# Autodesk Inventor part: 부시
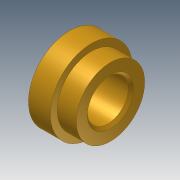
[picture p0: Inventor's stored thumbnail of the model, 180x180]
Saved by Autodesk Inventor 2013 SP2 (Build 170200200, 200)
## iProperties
Created: 2011-04
Part Number: 부시
Document SubType Name: Modeling
Density: 1 g/cm^3
Material: 일반
Author: pww
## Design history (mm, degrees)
sketch "스케치1"
  geometry: L1 (0, 0)-(15, 0); L2 (0, 7.5)-(15, 7.5); L3 (15, 7.5)-(15, 12.5); L4 (15, 12.5)-(8, 12.5); L5 (8, 12.5)-(8, 15); L6 (8, 15)-(0, 15); L7 (0, 15)-(0, 7.5)
  constraints: 14 end point, 4 parallel, 2 vertical alignment, 1 horizontal, 1 perpendicular, 1 vertical
  dimensions: "d0" = 15 distance of L1.start L1.end; "d1" = 15 diameter of L2 L1; "d2" = 25 diameter of L4 L1; "d3" = 8 distance of L5.end L6.end; "d4" = 30 diameter of L6 L1
revolve "회전1" sketch "스케치1" stored, may be unused: angle "d5" = 90 deg
chamfer "모따기1" distance "d6" = 1; stored, may be unused: second distance "d7" = 2, angle "d8" = 45 deg
node "솔리드1"
